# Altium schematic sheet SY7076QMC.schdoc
size 127 x 101 mm
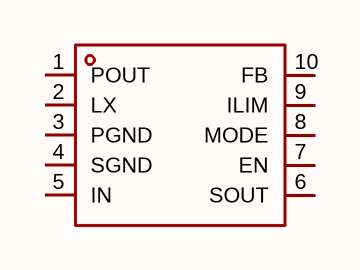
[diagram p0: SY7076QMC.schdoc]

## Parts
U?  sy7076qmc  [QFN-10_L2.0-W2.0_SY7066AQMC]  (value not drawn)

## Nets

Not connected (* = marked no-connect by the designer): U? 1(POUT) 2(LX) 3(PGND) 4(SGND) 5(IN) 6(SOUT) 7(EN) 8(MODE) 9(ILIM) 10(FB)

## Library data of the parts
U? = sy7076qmc: 功能类型:升压型;工作电压:2V~5.5V;输出电压:2.5V~5.5V;输出电流:1A;输出类型:可调;; Manufacturer: Silergy(矽力杰); AddInBom: yes; ModelId: 6bdd6ce538564a8d848b5bb8ea49d3d0; ModelName: QFN-10_L2.0-W2.0-H0.7_SY7066AQMC; ModelTransform: 79.527,79.1337,0,0,0,0,-2.241,-2.761,0; Function: 升压型; Output Current: 1A; Frequency - Switching: 500kHz; Synchronous Rectifier: 是; Number of Outputs: 1; Topology: 升压式; Quiescent Current: 10uA; Switch tube (built-in/external): 内置; Output Type: 可调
